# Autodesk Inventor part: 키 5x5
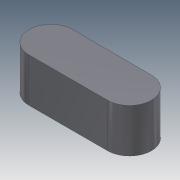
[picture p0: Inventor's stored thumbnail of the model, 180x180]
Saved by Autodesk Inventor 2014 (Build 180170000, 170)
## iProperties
Company: 한국ATC센터
Created: 2014-10
Part Number: 키 5x5
Document SubType Name: Modeling
Designer: KYOUNG IL JANG
Density: 7.85 g/cm^3
Mass: 2.53692 g
Surface Area: 2.9781 cm^2
Volume: 0.323175 cm^3
Material: 강철
Appearance: 강철 - 광택
Author: KYOUNG IL JANG
Revision Number: 1
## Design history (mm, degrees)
sketch "스케치1"
  geometry: L1 (-4.5, -2.5)-(4.5, -2.5); L2 (4.5, 2.5)-(-4.5, 2.5); A1 r 2.5 centre (4.5, 0) between (4.5, -2.5) and (4.5, 2.5); A2 r 2.5 centre (-4.5, 0) between (-4.5, 2.5) and (-4.5, -2.5); 2 further points
  constraints: 4 end point, 4 point on circle, 4 tangent, 2 centre point, 1 horizontal, 1 horizontal alignment, 1 midpoint, 1 parallel, 1 vertical alignment
  dimensions: "d0" = 5 distance between parallel lines of L1 L2; "d1" = 14 dimension on A1 A2
extrude "돌출1" new body sketch "스케치1" stored distance "d2" = 5; taper "d3" = 0 deg
node "솔리드1"
